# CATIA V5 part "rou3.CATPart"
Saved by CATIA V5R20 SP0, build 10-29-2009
Part number: rou3
Bounding box of the stored display mesh (mm): x 290 to 325, y -1051 to -1019, z 0.01 to 31.99
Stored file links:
  D:\Dropbox\Pack 1 sylvain\mmoreau\mmoreau\mmoreau\fin\rou3.CATPart
  U:\think motion\fin\think motion2.CATProduct
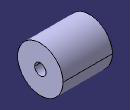
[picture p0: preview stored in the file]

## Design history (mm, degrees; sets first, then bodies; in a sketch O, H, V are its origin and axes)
Set1
  Plane1: linked copy from another document
  Point1: linked copy from another document
Body1 (main body)
  Sketch1 on Plane1, origin (325, 0, 0), H (0, 1, 0), V (0, 0, 1)
    circle A1 centre (-1035, 16) radius 16
    point P1 (-1035, 16)
    reference projected point E1 (-1035, 16) from Point1
    circle A2 centre (-1035, 16) radius 4
    point P2 (-1035, 16)
    reference projected point E2 (-1035, 16) from Point1
    radius A2 = 4
    coincidence: P1 E1, P2 E2
    tangency: A1 H
  Pad1: profile Sketch1, direction (-1, 0, 0), length 35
